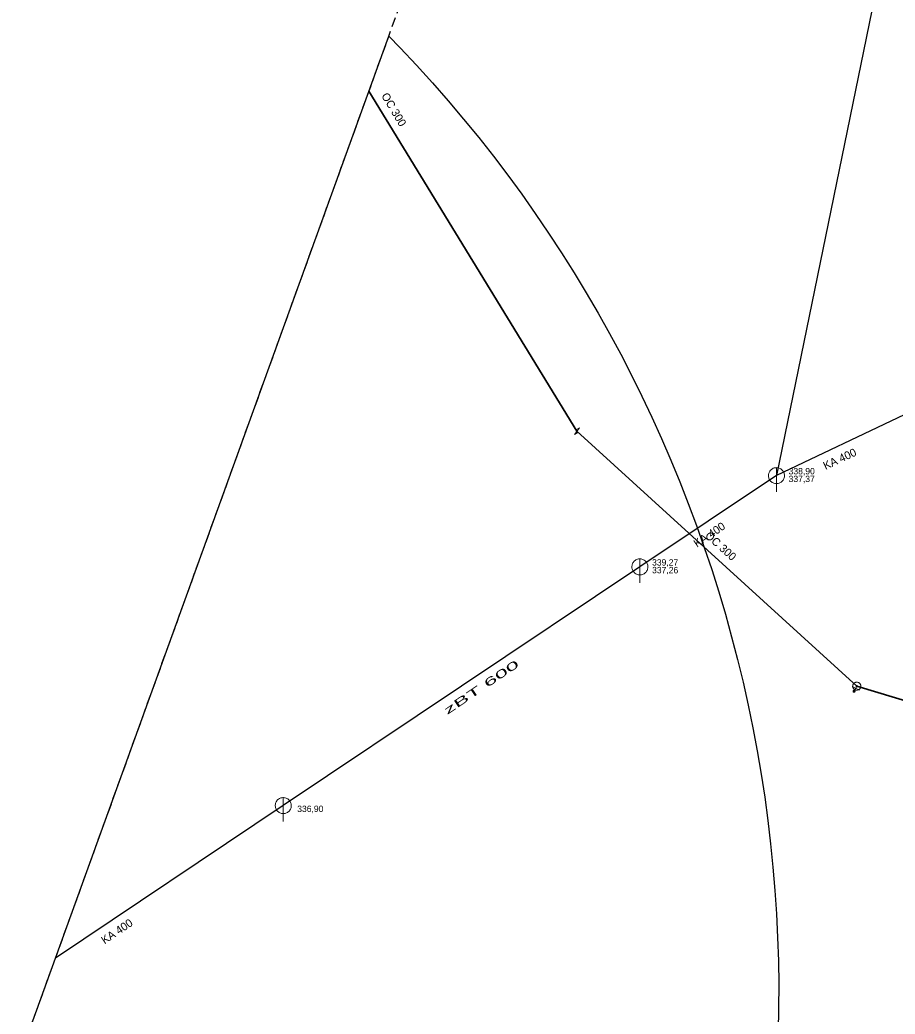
# Model space of a CAD drawing. Extents: x -724325 to -723665, y -972119 to -970722.
# Drawn here: x -724325.3 to -724215.9, y -971128.2 to -971004.1 of the extents above; entities that cross this region are included whole.
import ezdxf

# ---------------------------------------------------------------- set-up
doc = ezdxf.new("R2010")
doc.units = 0
doc.header["$LTSCALE"] = 0.4
doc.linetypes.add('MEDIUM_DASHED', pattern=[4.5, 3, -1.5])
for name, color, linetype, lineweight in [('1', 7, 'Continuous', 25), ('14', 7, 'Continuous', 25), ('17', 7, 'Continuous', 35), ('22', 7, 'Continuous', 13), ('34', 7, 'Continuous', 13), ('47', 7, 'Continuous', 13), ('9', 7, 'Continuous', 13)]:
    doc.layers.add(name, color=color, linetype=linetype, lineweight=lineweight)
doc.layers.add('19', color=7, linetype='Continuous')

msp = doc.modelspace()

# ---------------------------------------------------------------- linework, layer by layer
at = {"layer": '1', "linetype": 'MEDIUM_DASHED'}
msp.add_lwpolyline([(-724178.033, -970726.408), (-723849.368, -970722.221), (-723876.582, -971170.211), (-723665.148, -971503.063), (-723686.082, -972118.833), (-723917.752, -972118.833), (-723962.412, -971393.118), (-724325.27, -971133.535)], close=True, dxfattribs=at)
at = {"layer": '1'}
msp.add_lwpolyline([(-724325.27, -971133.535), (-724279.177, -971006.081), (-724277.767, -971007.531), (-724275.718, -971009.713), (-724273.711, -971011.925), (-724271.748, -971014.168), (-724269.827, -971016.441), (-724267.95, -971018.743), (-724266.116, -971021.074), (-724264.326, -971023.432), (-724262.579, -971025.818), (-724260.876, -971028.231), (-724259.217, -971030.669), (-724257.603, -971033.133), (-724256.033, -971035.621), (-724254.508, -971038.134), (-724253.028, -971040.67), (-724251.593, -971043.229), (-724250.203, -971045.81), (-724248.858, -971048.413), (-724247.56, -971051.036), (-724246.307, -971053.68), (-724245.1, -971056.344), (-724243.94, -971059.026), (-724242.826, -971061.727), (-724241.758, -971064.446), (-724240.738, -971067.182), (-724239.764, -971069.934), (-724238.838, -971072.703), (-724237.959, -971075.486), (-724237.128, -971078.284), (-724236.345, -971081.096), (-724235.609, -971083.922), (-724234.922, -971086.76), (-724234.283, -971089.61), (-724233.693, -971092.471), (-724233.152, -971095.343), (-724232.659, -971098.226), (-724232.216, -971101.118), (-724231.822, -971104.019), (-724231.478, -971106.928), (-724231.183, -971109.844), (-724230.939, -971112.768), (-724230.744, -971115.698), (-724230.6, -971118.634), (-724230.507, -971121.575), (-724230.464, -971124.52), (-724230.472, -971127.469), (-724230.531, -971130.421)], dxfattribs=at)
at = {"layer": '14'}
for p, q in [((-724216.066, -970989.491), (-724230.75, -971060.969)), ((-724214.78, -971053.379), (-724230.75, -971060.969)), ((-724230.75, -971060.969), (-724247.809, -971072.359)), ((-724247.809, -971072.359), (-724292.363, -971102.175)), ((-724292.363, -971102.175), (-724320.819, -971121.228))]:
    msp.add_line(p, q, dxfattribs=at)
at = {"layer": '14', "lineweight": 13}
for p, q in [((-724220.842, -971087.519), (-724221.059, -971087.89)), ((-724220.714, -971087.254), (-724220.842, -971087.519))]:
    msp.add_line(p, q, dxfattribs=at)
at = {"layer": '17'}
msp.add_line((-724255.679, -971055.409), (-724281.661, -971012.952), dxfattribs=at)
msp.add_lwpolyline([(-723856.75, -971277.52), (-723871.469, -971261.379), (-723894.09, -971234.91), (-723915.739, -971210.25), (-723934.449, -971190.379), (-723958.59, -971177.719), (-723983.8, -971165.17), (-724007.629, -971153.55), (-724038.03, -971139.35), (-724069.469, -971127.41), (-724098.62, -971120.079), (-724100.07, -971119.51), (-724120.89, -971115.66), (-724149.294, -971109.225), (-724187.32, -971097.32), (-724220.714, -971087.254), (-724255.679, -971055.409)], dxfattribs=at)
at = {"layer": '22'}
for p, q in [((-724230.75, -971062.969), (-724230.749, -971059.969)), ((-724247.809, -971074.359), (-724247.808, -971071.359)), ((-724292.363, -971104.175), (-724292.362, -971101.175))]:
    msp.add_line(p, q, dxfattribs=at)
for points in [[(-724229.75, -971060.969), (-724229.755, -971060.86), (-724229.773, -971060.752), (-724229.803, -971060.646), (-724229.843, -971060.545), (-724229.895, -971060.448), (-724229.957, -971060.358), (-724230.029, -971060.275), (-724230.109, -971060.201), (-724230.197, -971060.135), (-724230.291, -971060.08), (-724230.391, -971060.035), (-724230.496, -971060.002), (-724230.603, -971059.98), (-724230.712, -971059.97), (-724230.822, -971059.972), (-724230.93, -971059.986), (-724231.037, -971060.011), (-724231.14, -971060.048), (-724231.238, -971060.097), (-724231.33, -971060.155), (-724231.416, -971060.224), (-724231.493, -971060.301), (-724231.562, -971060.387), (-724231.621, -971060.479), (-724231.669, -971060.577), (-724231.706, -971060.68), (-724231.732, -971060.787), (-724231.746, -971060.895), (-724231.749, -971061.005), (-724231.739, -971061.114), (-724231.718, -971061.221), (-724231.684, -971061.325), (-724231.64, -971061.425), (-724231.585, -971061.52), (-724231.519, -971061.608), (-724231.445, -971061.688), (-724231.362, -971061.76), (-724231.272, -971061.822), (-724231.176, -971061.874), (-724231.074, -971061.915), (-724230.969, -971061.945), (-724230.861, -971061.963), (-724230.751, -971061.969), (-724230.642, -971061.963), (-724230.534, -971061.945), (-724230.429, -971061.916), (-724230.327, -971061.875), (-724230.23, -971061.823), (-724230.14, -971061.761), (-724230.057, -971061.69), (-724229.982, -971061.61), (-724229.917, -971061.522), (-724229.861, -971061.428), (-724229.817, -971061.328), (-724229.783, -971061.224), (-724229.761, -971061.116), (-724229.751, -971061.007)], [(-724246.809, -971072.359), (-724246.814, -971072.25), (-724246.832, -971072.142), (-724246.862, -971072.036), (-724246.902, -971071.935), (-724246.954, -971071.838), (-724247.016, -971071.748), (-724247.088, -971071.665), (-724247.168, -971071.591), (-724247.256, -971071.525), (-724247.35, -971071.47), (-724247.45, -971071.425), (-724247.555, -971071.392), (-724247.662, -971071.37), (-724247.771, -971071.36), (-724247.881, -971071.362), (-724247.989, -971071.376), (-724248.096, -971071.401), (-724248.199, -971071.438), (-724248.297, -971071.487), (-724248.389, -971071.545), (-724248.475, -971071.614), (-724248.552, -971071.691), (-724248.621, -971071.777), (-724248.68, -971071.869), (-724248.728, -971071.967), (-724248.765, -971072.07), (-724248.791, -971072.177), (-724248.805, -971072.285), (-724248.808, -971072.395), (-724248.798, -971072.504), (-724248.777, -971072.611), (-724248.743, -971072.715), (-724248.699, -971072.815), (-724248.644, -971072.91), (-724248.578, -971072.998), (-724248.504, -971073.078), (-724248.421, -971073.15), (-724248.331, -971073.212), (-724248.235, -971073.264), (-724248.133, -971073.305), (-724248.028, -971073.335), (-724247.92, -971073.353), (-724247.81, -971073.359), (-724247.701, -971073.353), (-724247.593, -971073.335), (-724247.488, -971073.306), (-724247.386, -971073.265), (-724247.289, -971073.213), (-724247.199, -971073.151), (-724247.116, -971073.08), (-724247.041, -971073), (-724246.976, -971072.912), (-724246.92, -971072.818), (-724246.876, -971072.718), (-724246.842, -971072.614), (-724246.82, -971072.506), (-724246.81, -971072.397)], [(-724291.363, -971102.175), (-724291.368, -971102.066), (-724291.386, -971101.958), (-724291.416, -971101.852), (-724291.456, -971101.751), (-724291.508, -971101.654), (-724291.57, -971101.564), (-724291.642, -971101.481), (-724291.722, -971101.407), (-724291.81, -971101.341), (-724291.904, -971101.286), (-724292.004, -971101.241), (-724292.109, -971101.208), (-724292.216, -971101.186), (-724292.325, -971101.176), (-724292.435, -971101.178), (-724292.543, -971101.192), (-724292.65, -971101.217), (-724292.753, -971101.254), (-724292.851, -971101.303), (-724292.943, -971101.361), (-724293.029, -971101.43), (-724293.106, -971101.507), (-724293.175, -971101.593), (-724293.234, -971101.685), (-724293.282, -971101.783), (-724293.319, -971101.886), (-724293.345, -971101.993), (-724293.359, -971102.101), (-724293.362, -971102.211), (-724293.352, -971102.32), (-724293.331, -971102.427), (-724293.297, -971102.531), (-724293.253, -971102.631), (-724293.198, -971102.726), (-724293.132, -971102.814), (-724293.058, -971102.894), (-724292.975, -971102.966), (-724292.885, -971103.028), (-724292.789, -971103.08), (-724292.687, -971103.121), (-724292.582, -971103.151), (-724292.474, -971103.169), (-724292.364, -971103.175), (-724292.255, -971103.169), (-724292.147, -971103.151), (-724292.042, -971103.122), (-724291.94, -971103.081), (-724291.843, -971103.029), (-724291.753, -971102.967), (-724291.67, -971102.896), (-724291.595, -971102.816), (-724291.53, -971102.728), (-724291.474, -971102.634), (-724291.43, -971102.534), (-724291.396, -971102.43), (-724291.374, -971102.322), (-724291.364, -971102.213)]]:
    msp.add_lwpolyline(points, close=True, dxfattribs=at)
at = {"layer": '34'}
msp.add_line((-724221.292, -971087.301), (-724220.392, -971087.737), dxfattribs=at)
at = {"layer": '47'}
msp.add_line((-724255.369, -971055.004), (-724255.812, -971055.258), dxfattribs=at)
msp.add_lwpolyline([(-724255.369, -971055.004), (-724255.988, -971055.813), (-724255.545, -971055.559)], dxfattribs=at)
for points in [[(-724220.214, -971087.254), (-724220.217, -971087.201), (-724220.225, -971087.149), (-724220.239, -971087.1), (-724220.257, -971087.051), (-724220.281, -971087.004), (-724220.31, -971086.96), (-724220.343, -971086.919), (-724220.38, -971086.882), (-724220.42, -971086.85), (-724220.464, -971086.821), (-724220.511, -971086.796), (-724220.56, -971086.779), (-724220.61, -971086.765), (-724220.662, -971086.757), (-724220.714, -971086.754), (-724220.766, -971086.757), (-724220.818, -971086.765), (-724220.869, -971086.779), (-724220.917, -971086.796), (-724220.964, -971086.821), (-724221.008, -971086.85), (-724221.049, -971086.882), (-724221.086, -971086.919), (-724221.119, -971086.96), (-724221.147, -971087.004), (-724221.171, -971087.051), (-724221.19, -971087.1), (-724221.203, -971087.149), (-724221.211, -971087.201), (-724221.214, -971087.254), (-724221.211, -971087.306), (-724221.203, -971087.358), (-724221.19, -971087.409), (-724221.171, -971087.456), (-724221.147, -971087.504), (-724221.119, -971087.548), (-724221.086, -971087.588), (-724221.049, -971087.625), (-724221.008, -971087.659), (-724220.964, -971087.686), (-724220.917, -971087.711), (-724220.869, -971087.73), (-724220.818, -971087.742), (-724220.766, -971087.75), (-724220.714, -971087.754), (-724220.662, -971087.75), (-724220.61, -971087.742), (-724220.56, -971087.73), (-724220.511, -971087.711), (-724220.464, -971087.686), (-724220.42, -971087.659), (-724220.38, -971087.625), (-724220.343, -971087.588), (-724220.31, -971087.548), (-724220.281, -971087.504), (-724220.257, -971087.456), (-724220.239, -971087.409), (-724220.225, -971087.358), (-724220.217, -971087.306)], [(-724220.632, -971087.254), (-724220.632, -971087.245), (-724220.634, -971087.237), (-724220.636, -971087.228), (-724220.639, -971087.22), (-724220.643, -971087.213), (-724220.648, -971087.206), (-724220.653, -971087.198), (-724220.659, -971087.193), (-724220.666, -971087.188), (-724220.673, -971087.183), (-724220.681, -971087.179), (-724220.689, -971087.176), (-724220.697, -971087.174), (-724220.705, -971087.171), (-724220.714, -971087.171), (-724220.723, -971087.171), (-724220.731, -971087.174), (-724220.739, -971087.176), (-724220.747, -971087.179), (-724220.755, -971087.183), (-724220.762, -971087.188), (-724220.769, -971087.193), (-724220.775, -971087.198), (-724220.781, -971087.206), (-724220.785, -971087.213), (-724220.789, -971087.22), (-724220.792, -971087.228), (-724220.794, -971087.237), (-724220.796, -971087.245), (-724220.796, -971087.254), (-724220.796, -971087.262), (-724220.794, -971087.271), (-724220.792, -971087.279), (-724220.789, -971087.287), (-724220.785, -971087.294), (-724220.781, -971087.301), (-724220.775, -971087.309), (-724220.769, -971087.315), (-724220.762, -971087.321), (-724220.755, -971087.325), (-724220.747, -971087.328), (-724220.739, -971087.331), (-724220.731, -971087.333), (-724220.723, -971087.336), (-724220.714, -971087.336), (-724220.705, -971087.336), (-724220.697, -971087.333), (-724220.689, -971087.331), (-724220.681, -971087.328), (-724220.673, -971087.325), (-724220.666, -971087.321), (-724220.659, -971087.315), (-724220.653, -971087.309), (-724220.648, -971087.301), (-724220.643, -971087.294), (-724220.639, -971087.287), (-724220.636, -971087.279), (-724220.634, -971087.271), (-724220.632, -971087.262)]]:
    msp.add_lwpolyline(points, close=True, dxfattribs=at)
at = {"layer": '9'}
for points in [[(-724221.185, -971087.89), (-724221.185, -971087.903), (-724221.183, -971087.916), (-724221.18, -971087.929), (-724221.175, -971087.941), (-724221.169, -971087.953), (-724221.162, -971087.964), (-724221.154, -971087.974), (-724221.144, -971087.984), (-724221.134, -971087.992), (-724221.123, -971087.999), (-724221.111, -971088.005), (-724221.099, -971088.01), (-724221.086, -971088.013), (-724221.073, -971088.015), (-724221.06, -971088.017), (-724221.047, -971088.016), (-724221.034, -971088.014), (-724221.021, -971088.011), (-724221.009, -971088.006), (-724220.997, -971088), (-724220.986, -971087.993), (-724220.976, -971087.985), (-724220.966, -971087.975), (-724220.958, -971087.965), (-724220.951, -971087.954), (-724220.945, -971087.942), (-724220.94, -971087.93), (-724220.937, -971087.917), (-724220.935, -971087.904), (-724220.933, -971087.891), (-724220.934, -971087.878), (-724220.936, -971087.865), (-724220.939, -971087.852), (-724220.944, -971087.84), (-724220.95, -971087.828), (-724220.957, -971087.817), (-724220.965, -971087.807), (-724220.975, -971087.797), (-724220.985, -971087.789), (-724220.996, -971087.782), (-724221.008, -971087.776), (-724221.02, -971087.771), (-724221.033, -971087.768), (-724221.046, -971087.766), (-724221.059, -971087.765), (-724221.072, -971087.765), (-724221.085, -971087.767), (-724221.098, -971087.77), (-724221.11, -971087.775), (-724221.122, -971087.781), (-724221.133, -971087.788), (-724221.143, -971087.796), (-724221.153, -971087.806), (-724221.161, -971087.816), (-724221.168, -971087.827), (-724221.174, -971087.839), (-724221.179, -971087.851), (-724221.182, -971087.864), (-724221.184, -971087.877)], [(-724221.165, -971087.89), (-724221.166, -971087.901), (-724221.164, -971087.912), (-724221.161, -971087.923), (-724221.157, -971087.933), (-724221.152, -971087.943), (-724221.146, -971087.952), (-724221.139, -971087.961), (-724221.131, -971087.969), (-724221.122, -971087.976), (-724221.113, -971087.982), (-724221.103, -971087.987), (-724221.093, -971087.991), (-724221.082, -971087.994), (-724221.071, -971087.997), (-724221.06, -971087.997), (-724221.049, -971087.997), (-724221.038, -971087.995), (-724221.027, -971087.992), (-724221.017, -971087.988), (-724221.007, -971087.983), (-724220.998, -971087.977), (-724220.989, -971087.97), (-724220.981, -971087.962), (-724220.974, -971087.953), (-724220.968, -971087.944), (-724220.963, -971087.934), (-724220.959, -971087.924), (-724220.956, -971087.913), (-724220.954, -971087.902), (-724220.953, -971087.891), (-724220.953, -971087.88), (-724220.955, -971087.869), (-724220.958, -971087.858), (-724220.962, -971087.848), (-724220.967, -971087.838), (-724220.973, -971087.829), (-724220.98, -971087.82), (-724220.988, -971087.812), (-724220.997, -971087.805), (-724221.006, -971087.799), (-724221.016, -971087.794), (-724221.026, -971087.79), (-724221.037, -971087.787), (-724221.048, -971087.785), (-724221.059, -971087.785), (-724221.07, -971087.784), (-724221.081, -971087.786), (-724221.092, -971087.789), (-724221.102, -971087.793), (-724221.112, -971087.798), (-724221.121, -971087.804), (-724221.13, -971087.811), (-724221.138, -971087.819), (-724221.145, -971087.828), (-724221.151, -971087.837), (-724221.156, -971087.847), (-724221.16, -971087.857), (-724221.163, -971087.868), (-724221.165, -971087.879)], [(-724221.146, -971087.89), (-724221.146, -971087.899), (-724221.145, -971087.908), (-724221.142, -971087.917), (-724221.139, -971087.925), (-724221.135, -971087.933), (-724221.13, -971087.941), (-724221.124, -971087.948), (-724221.118, -971087.954), (-724221.111, -971087.96), (-724221.103, -971087.965), (-724221.095, -971087.969), (-724221.087, -971087.972), (-724221.078, -971087.975), (-724221.069, -971087.976), (-724221.06, -971087.978), (-724221.051, -971087.977), (-724221.042, -971087.976), (-724221.033, -971087.973), (-724221.025, -971087.97), (-724221.017, -971087.966), (-724221.009, -971087.961), (-724221.002, -971087.955), (-724220.996, -971087.949), (-724220.99, -971087.942), (-724220.985, -971087.934), (-724220.981, -971087.926), (-724220.978, -971087.918), (-724220.975, -971087.909), (-724220.974, -971087.9), (-724220.972, -971087.891), (-724220.973, -971087.882), (-724220.974, -971087.873), (-724220.977, -971087.864), (-724220.98, -971087.856), (-724220.984, -971087.848), (-724220.989, -971087.84), (-724220.995, -971087.833), (-724221.001, -971087.827), (-724221.008, -971087.821), (-724221.016, -971087.816), (-724221.024, -971087.812), (-724221.032, -971087.809), (-724221.041, -971087.806), (-724221.05, -971087.805), (-724221.059, -971087.804), (-724221.068, -971087.804), (-724221.077, -971087.805), (-724221.086, -971087.808), (-724221.094, -971087.811), (-724221.102, -971087.815), (-724221.11, -971087.82), (-724221.117, -971087.826), (-724221.123, -971087.832), (-724221.129, -971087.839), (-724221.134, -971087.847), (-724221.138, -971087.855), (-724221.141, -971087.863), (-724221.144, -971087.872), (-724221.145, -971087.881)], [(-724221.126, -971087.89), (-724221.126, -971087.897), (-724221.125, -971087.904), (-724221.124, -971087.911), (-724221.121, -971087.917), (-724221.118, -971087.923), (-724221.114, -971087.929), (-724221.11, -971087.935), (-724221.105, -971087.94), (-724221.099, -971087.944), (-724221.093, -971087.948), (-724221.087, -971087.951), (-724221.081, -971087.954), (-724221.074, -971087.955), (-724221.067, -971087.958), (-724221.06, -971087.958), (-724221.053, -971087.958), (-724221.046, -971087.956), (-724221.039, -971087.955), (-724221.033, -971087.952), (-724221.026, -971087.949), (-724221.021, -971087.945), (-724221.015, -971087.941), (-724221.01, -971087.936), (-724221.006, -971087.93), (-724221.002, -971087.924), (-724220.999, -971087.918), (-724220.996, -971087.912), (-724220.994, -971087.905), (-724220.993, -971087.898), (-724220.992, -971087.891), (-724220.992, -971087.884), (-724220.993, -971087.877), (-724220.995, -971087.87), (-724220.998, -971087.864), (-724221.001, -971087.857), (-724221.005, -971087.852), (-724221.009, -971087.846), (-724221.014, -971087.841), (-724221.02, -971087.837), (-724221.025, -971087.833), (-724221.032, -971087.83), (-724221.038, -971087.827), (-724221.045, -971087.825), (-724221.052, -971087.824), (-724221.059, -971087.824), (-724221.066, -971087.824), (-724221.073, -971087.824), (-724221.08, -971087.826), (-724221.086, -971087.829), (-724221.092, -971087.832), (-724221.098, -971087.836), (-724221.104, -971087.84), (-724221.109, -971087.845), (-724221.113, -971087.851), (-724221.117, -971087.856), (-724221.12, -971087.863), (-724221.123, -971087.869), (-724221.124, -971087.876), (-724221.126, -971087.883)], [(-724221.106, -971087.89), (-724221.106, -971087.895), (-724221.106, -971087.9), (-724221.105, -971087.905), (-724221.103, -971087.909), (-724221.101, -971087.914), (-724221.098, -971087.918), (-724221.095, -971087.921), (-724221.091, -971087.925), (-724221.088, -971087.928), (-724221.084, -971087.931), (-724221.079, -971087.933), (-724221.075, -971087.935), (-724221.07, -971087.936), (-724221.065, -971087.938), (-724221.06, -971087.938), (-724221.055, -971087.938), (-724221.05, -971087.937), (-724221.045, -971087.936), (-724221.041, -971087.934), (-724221.036, -971087.932), (-724221.032, -971087.929), (-724221.028, -971087.926), (-724221.025, -971087.922), (-724221.022, -971087.919), (-724221.019, -971087.915), (-724221.017, -971087.91), (-724221.015, -971087.906), (-724221.014, -971087.901), (-724221.013, -971087.896), (-724221.012, -971087.891), (-724221.012, -971087.886), (-724221.013, -971087.881), (-724221.014, -971087.876), (-724221.016, -971087.872), (-724221.018, -971087.867), (-724221.021, -971087.863), (-724221.024, -971087.859), (-724221.027, -971087.856), (-724221.031, -971087.853), (-724221.035, -971087.85), (-724221.04, -971087.848), (-724221.044, -971087.846), (-724221.049, -971087.845), (-724221.054, -971087.844), (-724221.059, -971087.844), (-724221.064, -971087.844), (-724221.069, -971087.845), (-724221.074, -971087.845), (-724221.078, -971087.847), (-724221.083, -971087.849), (-724221.087, -971087.852), (-724221.09, -971087.855), (-724221.094, -971087.858), (-724221.097, -971087.862), (-724221.1, -971087.866), (-724221.102, -971087.871), (-724221.104, -971087.875), (-724221.105, -971087.88), (-724221.106, -971087.885)], [(-724221.086, -971087.89), (-724221.086, -971087.893), (-724221.087, -971087.896), (-724221.086, -971087.898), (-724221.085, -971087.901), (-724221.084, -971087.904), (-724221.082, -971087.906), (-724221.08, -971087.908), (-724221.078, -971087.91), (-724221.076, -971087.912), (-724221.074, -971087.914), (-724221.071, -971087.916), (-724221.068, -971087.917), (-724221.066, -971087.917), (-724221.063, -971087.918), (-724221.06, -971087.918), (-724221.057, -971087.918), (-724221.054, -971087.918), (-724221.051, -971087.917), (-724221.049, -971087.916), (-724221.046, -971087.915), (-724221.044, -971087.913), (-724221.041, -971087.911), (-724221.039, -971087.909), (-724221.038, -971087.907), (-724221.036, -971087.905), (-724221.035, -971087.902), (-724221.033, -971087.899), (-724221.033, -971087.897), (-724221.032, -971087.894), (-724221.031, -971087.891), (-724221.032, -971087.888), (-724221.032, -971087.885), (-724221.033, -971087.882), (-724221.034, -971087.88), (-724221.035, -971087.877), (-724221.037, -971087.875), (-724221.038, -971087.872), (-724221.04, -971087.87), (-724221.043, -971087.869), (-724221.045, -971087.867), (-724221.048, -971087.866), (-724221.05, -971087.865), (-724221.053, -971087.864), (-724221.056, -971087.864), (-724221.059, -971087.863), (-724221.062, -971087.864), (-724221.065, -971087.863), (-724221.067, -971087.865), (-724221.07, -971087.865), (-724221.073, -971087.866), (-724221.075, -971087.868), (-724221.077, -971087.869), (-724221.079, -971087.871), (-724221.081, -971087.874), (-724221.083, -971087.876), (-724221.084, -971087.879), (-724221.085, -971087.881), (-724221.086, -971087.884), (-724221.086, -971087.887)], [(-724221.067, -971087.89), (-724221.067, -971087.892), (-724221.067, -971087.892), (-724221.066, -971087.892), (-724221.066, -971087.894), (-724221.067, -971087.895), (-724221.065, -971087.895), (-724221.065, -971087.895), (-724221.065, -971087.897), (-724221.065, -971087.897), (-724221.064, -971087.898), (-724221.062, -971087.898), (-724221.062, -971087.898), (-724221.062, -971087.899), (-724221.06, -971087.899), (-724221.06, -971087.899), (-724221.059, -971087.899), (-724221.058, -971087.899), (-724221.058, -971087.898), (-724221.057, -971087.898), (-724221.055, -971087.898), (-724221.055, -971087.897), (-724221.055, -971087.897), (-724221.054, -971087.896), (-724221.054, -971087.896), (-724221.052, -971087.895), (-724221.052, -971087.894), (-724221.051, -971087.893), (-724221.051, -971087.893), (-724221.051, -971087.892), (-724221.051, -971087.891), (-724221.051, -971087.89), (-724221.051, -971087.889), (-724221.051, -971087.889), (-724221.052, -971087.888), (-724221.052, -971087.887), (-724221.053, -971087.886), (-724221.053, -971087.886), (-724221.054, -971087.885), (-724221.054, -971087.885), (-724221.055, -971087.884), (-724221.056, -971087.884), (-724221.057, -971087.883), (-724221.057, -971087.883), (-724221.058, -971087.883), (-724221.059, -971087.883), (-724221.06, -971087.883), (-724221.061, -971087.883), (-724221.061, -971087.883), (-724221.062, -971087.884), (-724221.063, -971087.883), (-724221.064, -971087.885), (-724221.064, -971087.885), (-724221.065, -971087.885), (-724221.065, -971087.885), (-724221.066, -971087.887), (-724221.066, -971087.888), (-724221.066, -971087.889), (-724221.067, -971087.889), (-724221.067, -971087.89)]]:
    msp.add_lwpolyline(points, close=True, dxfattribs=at)

# ---------------------------------------------------------------- texts
at = {"layer": '1'}
for s, rotation, p in [('OC 300', 301, (-724280.154, -971013.527)), ('KA 400', 25, (-724224.621, -971060.255)), ('KA 400', 34, (-724240.672, -971069.981)), ('OC 300', 318, (-724239.75, -971068.582)), ('KA 400', 34, (-724314.688, -971119.512))]:
    msp.add_text(s, height=1, rotation=rotation, dxfattribs=at).set_placement(p)
at = {"layer": '1', "width": 2.2}
msp.add_text('zBT 600 ', height=1, rotation=34, dxfattribs=at).set_placement((-724271.89, -971090.863))
at = {"layer": '19'}
for s, p in [('338,90', (-724229.228, -971060.81)), ('337,37', (-724229.228, -971061.77)), ('339,27', (-724246.288, -971072.2)), ('337,26', (-724246.288, -971073.16)), ('336,90', (-724290.62, -971102.974))]:
    msp.add_text(s, height=0.8, dxfattribs=at).set_placement(p)

doc.saveas('drawing.dxf')
